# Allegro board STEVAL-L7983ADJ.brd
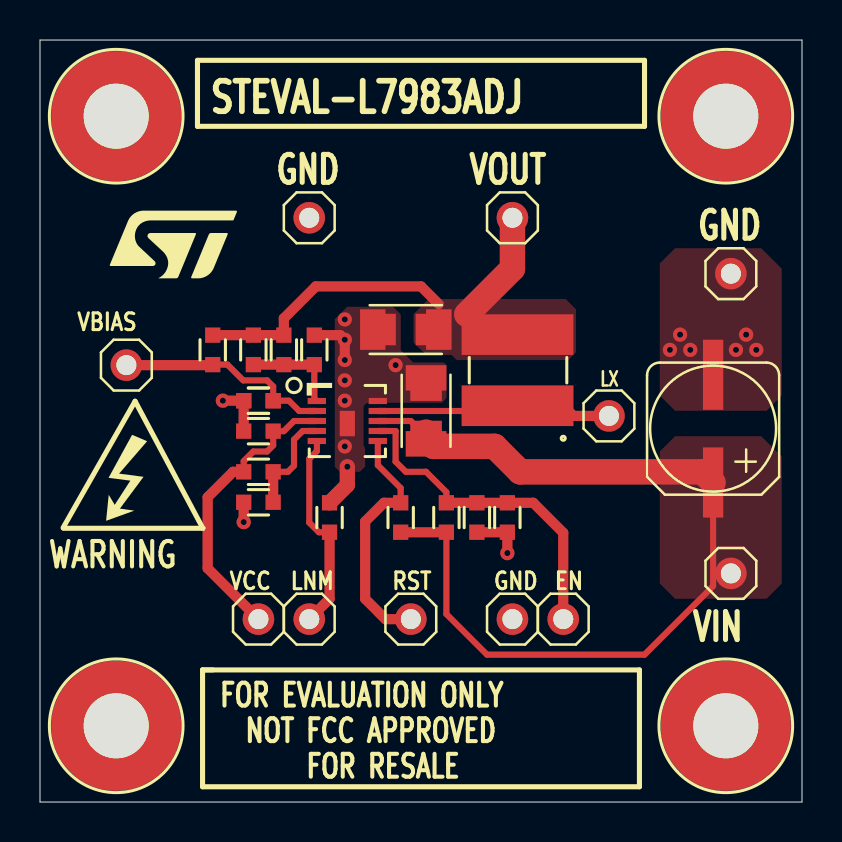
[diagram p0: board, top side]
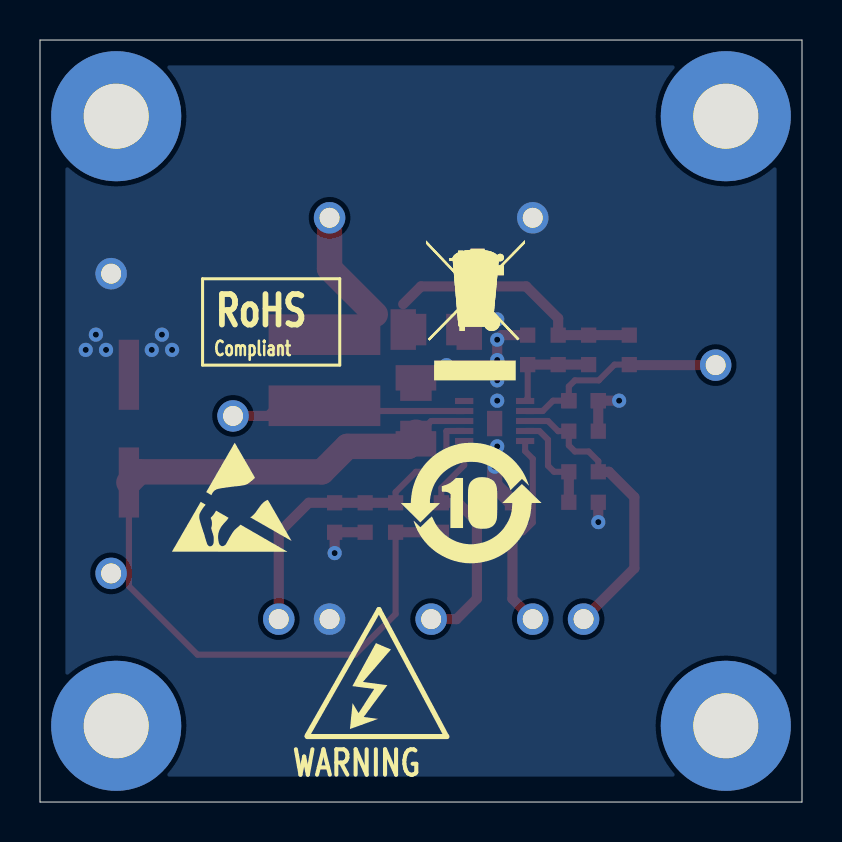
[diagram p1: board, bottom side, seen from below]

Outline 38.1 x 38.1 mm; copper layers: TOP, BOTTOM. Coordinates in mm from the lower left corner of the outline.
Outline path: 0,38.1 38.1,38.1 38.1,0 0,0 0,38.1

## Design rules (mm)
constraint set DEFAULT: min track width 0.203

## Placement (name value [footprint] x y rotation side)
C1  1uF  [C0805_1206_T]  19.3 19.56 270 top
C2  1uF  [C0805_1206_T]  18.29 23.62 0 top
C3  470nF  [CAPC-0603]  10.92 18.54 0 top
C4  NM  [CAPC-0603]  10.67 22.61 270 top
C5  NM  [CAPC-0603]  21.84 14.22 90 top
C6  100nF  [CAPC-0603]  10.92 20.07 0 top
C10  Radial 6.3mm-SMD  [CEVSMD_6V3X8_T]  33.66 18.67 270 top
L1  33uH  [IND_LPS4018_LPS5030]  23.88 21.59 90 top
NOREF  -  []  2.54 24.38 0 top
NOREF#2  -  []  141.76 49.5 0 top
NOREF#3  -  []  232.92 -22.73 0 top
NOREF#4  -  [unnamed#2]  3.81 3.81 0 top
NOREF#5  -  []  0 0 90 top
NOREF#6  -  []  -32.31 -137.72 90 top
NOREF#7  -  []  231.9 -22.73 0 top
NOREF#8  -  []  67.13 -139.83 0 top
NOREF#9  -  []  -32.33 46.99 90 top
NOREF#10  -  []  164.59 -139.83 0 top
NOREF#11  -  []  0 50.8 0 top
NOREF#12  -  []  -32.31 0.81 90 top
NOREF#13  -  []  -32.31 -45.36 90 top
NOREF#14  -  []  -32.31 -91.54 90 top
NOREF#15  -  []  164.44 -139.83 0 top
NOREF#16  -  []  -32.38 -139.83 90 top
NOREF#17  -  []  -31.75 46.99 90 top
NOREF#18  -  []  -76.83 -213.74 0 top
NOREF#19  -  []  115.8 -139.83 0 top
NOREF#20  -  []  -32.31 0.81 90 top
NOREF#21  -  [unnamed#2]  34.29 3.81 0 top
NOREF#22  -  []  142.83 -138.54 0 top
NOREF#23  -  []  229.36 -33.91 0 top
NOREF#24  -  []  6.1 14.48 0 top
NOREF#25  -  []  -32.31 -137.72 90 top
NOREF#26  -  []  -32.38 -139.83 0 top
NOREF#27  -  [unnamed#2]  34.29 34.29 0 top
NOREF#28  -  [unnamed#2]  3.81 34.29 0 top
NOREF#29  -  []  18.47 -139.83 0 top
NOREF#30  -  []  -23.5 49.53 0 top
NOREF#31  -  []  19.81 4.06 180 bottom
NOREF#32  -  []  18.8 21.08 180 bottom
NOREF#33  -  []  31.5 8.89 180 bottom
NOREF#34  -  []  20.07 11.94 180 bottom
NOREF#35  -  []  19.91 39.85 180 bottom
R1  510k  [RESC-0603]  12.19 22.61 90 top
R2  39k  [RESC-0603]  13.72 22.61 270 top
R3  N.M.  [RESC-0603]  10.92 16.51 180 top
R4  0R  [RESC-0603]  10.92 14.99 0 top
R5  100k  [RESC-0603]  18.03 14.22 270 top
R6  100k  [RESC-0603]  20.32 14.22 270 top
R7  N.M.  [RESC-0603]  23.37 14.22 90 top
R8  100k  [RESC-0603]  14.48 14.22 270 top
R9  0R  [RESC-0603]  8.64 22.61 270 top
R10  N.M.  [RESC-0603]  10.92 20.07 0 top
TP1  GND  [STRIP1]  37.08 27.69 90 top
TP2  VIN  [STRIP1]  37.08 12.7 90 top
TP3  VOUT  [STRIP1]  24.89 26.67 0 top
TP4  GND  [STRIP1]  14.73 26.67 0 top
TP5  LX  [STRIP1]  29.72 16.76 0 top
TP6  ENABLE  [STRIP1]  27.43 6.6 0 top
TP7  LNM-LCM  [STRIP1]  14.73 6.6 0 top
TP8  GND  [STRIP1]  24.89 6.6 0 top
TP9  RESET  [STRIP1]  19.81 6.6 0 top
TP11  VCC  [STRIP1]  12.19 6.6 0 top
TP12  VBIAS  [STRIP1]  5.59 19.3 0 top
U1  L7983PUR  [DFN3X3_L7983]  15.37 19.05 0 top

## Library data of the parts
C1 C2 = CNP_2: User Part Number: ***; Tolerance: ***
C3-C6 = CNP_2
C10 = CAP Radial 6.3mm-SMD: Tolerance: ***; User Part Number: ***
L1 = INDC-COILCRAFT-MSS1246
R1-R10 = R
TP1-TP9 TP11 TP12 = TP 0.9mm
U1 = L7983_DFN10_3x3

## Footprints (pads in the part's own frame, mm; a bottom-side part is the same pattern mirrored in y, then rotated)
C0805_1206_T
  rect 1.143x1.575 smd: 1(1.067,0) 2(-1.067,0)
CAPC-0603
  rect 0.762x0.762 smd: 1(-0.737,0) 2(0.737,0)
CEVSMD_6V3X8_T
  rect 3.505x1.016 smd: N(-2.692,0) P(2.692,0)
DFN3X3_L7983
  rect 0.914x0.305 smd: 1(-1.524,1) 2(-1.524,0.5) 3(-1.524,0) 4(-1.524,-0.5) 5(-1.524,-1) 6(1.524,-1) 7(1.524,-0.5) 8(1.524,0) 9(1.524,0.5) 10(1.524,1)
  rect 0.762x1.27 smd: 11(0,-0.127)
IND_LPS4018_LPS5030
  rect 2.032x5.588 smd: 1(-1.778,0) 2(1.778,0)
RESC-0603
  rect 0.762x0.762 smd: 1(-0.737,0) 2(0.737,0)
STRIP1
  round 1.575 hole 1: 1(-1.27,2.54)
unnamed#2
  round 6.502 hole 3.251: 1(0,0)

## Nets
GND: C1.2 C2.2 C3.1 C5.1 C6.1 C10.N R2.1 R4.1 R7.1 R8.1 R10.1 TP1.1 TP4.1 TP8.1 U1.10 U1.11
VCC: C3.2 R3.2 TP11.1 U1.3
VIN: C1.1 C10.P R5.2 R6.2 TP2.1 U1.8
ENABLE: C5.2 R6.1 R7.2 TP6.1 U1.7
FSW: R3.1 R4.2 U1.4
LNM-LCM: R8.2 TP7.1 U1.5
RESET: R5.1 TP9.1 U1.6
VBIAS: C6.2 R9.2 R10.2 TP12.1 U1.2
VOUT: C2.1 C4.1 L1.2 R1.2 R9.1 TP3.1
N3652199: L1.1 TP5.1 U1.9
N3652645: C4.2 R1.1 R2.2 U1.1(VOUT/FB)

Pads without a net: NOREF#4 1; NOREF#21 1; NOREF#27 1; NOREF#28 1

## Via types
v1: diameter 0.711, hole 0.305, TOP to BOTTOM, 17 vias

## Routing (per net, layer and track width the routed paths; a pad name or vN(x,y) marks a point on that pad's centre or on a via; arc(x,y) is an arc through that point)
GND: length 10.9
  TOP w0.508: v1(23.37,12.45) R7.1 C5.1 ; v1(15.24,22.1) v1(15.24,23.11) 15.01,23.34 R2.1 ; C3.1 R10.1 v1(9.14,20.07) ; R4.1 v1(10.19,14)
  TOP w0.762: R8.1 15.37,15.85 v1(15.37,16.76)
  vias: v1(15.24,24.13) v1(15.24,21.08) v1(15.24,20.07) v1(15.24,17.78) v1(17.78,21.84) v1(31.5,22.61) v1(32,23.37) v1(32.51,22.61) v1(34.8,22.61) v1(35.31,23.37) v1(35.81,22.61)
VCC: length 14.9
  TOP w0.305: R3.2 10.19,17.04 10.67,17.53 11.35,17.53 11.66,17.83 C3.2 12.19,18.54 12.7,19.05 U1.3
  TOP w0.508: TP11.1 8.38,11.68 8.38,15.24 9.65,16.51 R3.2
VIN: length 45.4
  TOP w0.305: U1.8 18.54,19.05 19.1,18.49 C1.1 ; R6.2 20.32,9.4 22.35,7.37 30.23,7.37 33.66,10.79 C10.P
  TOP w0.508: R5.2 R6.2
  TOP w1.27: C1.1 19.3,18.16 19.68,17.78 22.73,17.78 24,16.51 33.12,16.51 C10.P
ENABLE: length 16.9
  TOP w0.305: R6.1 20.32,15.49 19.3,16.51 18.29,16.51 17.78,17.02 17.78,18.54 17.77,18.55 U1.7
  TOP w0.508: TP6.1 26.16,13.46 24.66,14.96 R7.2 C5.2 R6.1
FSW: length 5.3
  TOP w0.305: R3.1 12.4,16.51 12.7,16.81 12.7,18.12 13.13,18.55 U1.4
  TOP w0.508: R3.1 R4.2
LNM-LCM: length 10.2
  TOP w0.305: R8.2 13.94,13.49 13.46,13.97 13.46,17.16 13.84,17.54 U1.5
  TOP w0.508: TP7.1 14.48,10.16 R8.2
RESET: length 12.3
  TOP w0.305: U1.6 16.89,16.84 18.03,15.7 R5.1
  TOP w0.508: R5.1 17.2,14.96 16.26,14.02 16.26,10.16 17.27,9.14 TP9.1
VBIAS: length 10.9
  TOP w0.305: R9.2 9.37,21.87 10.16,21.08 11.35,21.08 11.66,20.78 R10.2 12.45,20.07 12.96,19.55 U1.2
  TOP w0.508: R9.2 8.61,21.84 TP12.1
VOUT: length 18.9
  TOP w0.508: R9.1 C4.1 R1.2 12.19,24.18 13.79,25.78 19.05,25.78 19.94,24.89
  TOP w1.27: TP3.1 23.62,26.67 21.34,24.38
N3652199: length 11.9
  TOP w0.305: 23.11,19.86 22.9,19.86 22.6,19.55 U1.9
  TOP w0.508: TP5.1 26.67,19.3 26.16,19.81 L1.1 23.16,19.81 23.11,19.86
N3652645: length 4.9
  TOP w0.305: U1.1 13.72,20.18 R2.2
  TOP w0.508: C4.2 R1.1 R2.2

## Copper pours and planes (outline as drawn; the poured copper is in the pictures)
GND on TOP (solid shape): 17.27,22.61 16,22.61 16,24.64 17.27,24.64
GND on TOP (solid shape): 20.32,20.57 18.29,20.57 18.29,21.84 20.32,21.84
GND on TOP: 16.51,19.94 16.26,19.68 16.26,16.76 16,16.51 14.99,16.51 14.73,16.76 14.73,24.13 15.37,24.77 17.65,24.77 18.03,24.38 18.03,22.61 18.67,21.97 20.19,21.97 20.32,21.84 20.32,20.19 20.07,19.94
GND on TOP: 31.75,27.69 36.07,27.69 37.08,26.67 37.08,20.32 36.32,19.56 31.75,19.56 30.99,20.32 30.99,26.92
GND on BOTTOM: 36.83,1.27 1.27,1.27 1.27,36.83 36.83,36.83
VIN on TOP (solid shape): 20.32,17.27 18.29,17.27 18.29,18.54 20.32,18.54
VIN on TOP: 31.75,18.29 36.07,18.29 37.08,17.27 37.08,10.92 36.32,10.16 31.75,10.16 30.99,10.92 30.99,17.53
VOUT on TOP (solid shape): 20.57,22.61 19.3,22.61 19.3,24.64 20.57,24.64
VOUT on TOP: 19.43,25.15 18.67,24.38 18.67,22.99 19.3,22.35 20.57,22.35 20.83,22.1 26.42,22.1 26.8,22.48 26.8,24.64 26.29,25.15

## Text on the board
Ref Des/Silkscreen Bottom: Compliant | RoHS
Ref Des/Silkscreen Top: LX | VBIAS | VCC | LNM | RST | GND | EN | FOR EVALUATION ONLY | NOT FCC APPROVED | FOR RESALE | VOUT | VIN | STEVAL-L7983ADJ
PANNELLO: COPPER AREA ON OPPOSITE SIDE | 180 MILS | ENGRAVE TROUGH DISK CUTTER | +0.05mm | -0.05mm | +20 | -20 | PUT FOUR FIDUCIAL MARKS ON COMPONENTS SIDE | PUT A COPPER AREA ON SOLDER SIDE BELOW THE FID. MARK | cu DIAMETER 60 MILS | Solder mask opening 137 mils | SCHEDA1 | SCHEDA5 | SCHEDA9 | SCHEDA13 | SCHEDA2 | SCHEDA6 | SCHEDA10 | SCHEDA14 | SCHEDA3 | SCHEDA7 | SCHEDA11 | SCHEDA15 | SCHEDA4 | SCHEDA8 | SCHEDA12 | SCHEDA16 | IFARCAD Srl | 28/02/13 | L6984 VFQFPN10 4X4 | ESEMPIO DI PANNELLO | L69844X4 | 1.0
User.12: FIGURE | FINISHED_SIZE | 12.0 | 39.37 | 128.0 | DRILL CHART: TOP to BOTTOM | ALL UNITS ARE IN MILS | PLATED | QTY | 10 | 12 | 4
User.14: PIANO DI MONTAGGIO | 1.0 | L6984 VFQFPN 4X4 | L69844X4
